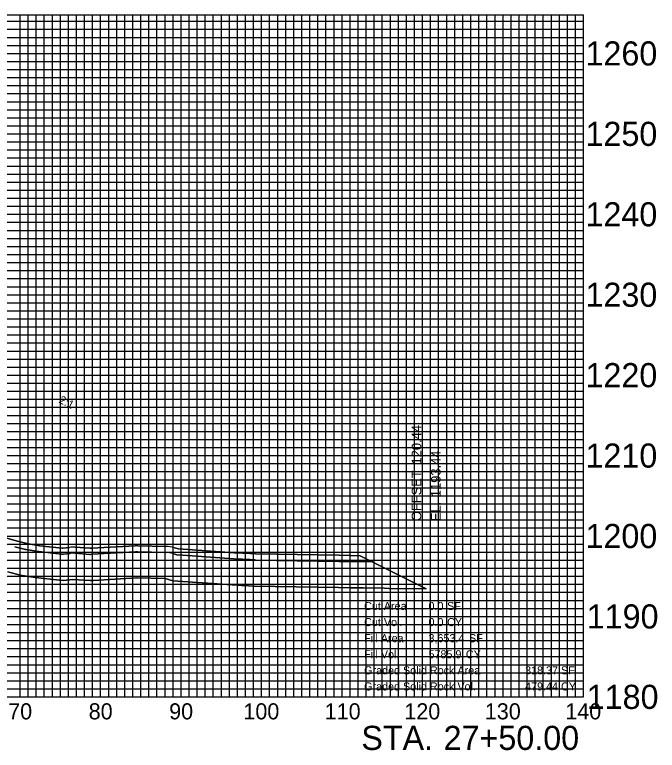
# Model space of a CAD drawing. Extents: x -109 to 149, y 1173 to 1269.
# Drawn here: x 69.3 to 149.2, y 1173.4 to 1264.8 of the extents above; entities that cross this region are included whole.
import ezdxf

# ---------------------------------------------------------------- set-up
doc = ezdxf.new("R2010")
doc.units = 0
for name, color, linetype in [('DES - SHEET - Light Grid', 7, 'Continuous'), ('DES - SHEET - Linework', 7, 'Continuous'), ('DES - TRAN - Proposed Layout Patterning', 7, 'Continuous'), ('DES - XS - Proposed - Finished Grade Slopes Text', 7, 'Continuous'), ('DES - XS - Proposed - Text', 7, 'Continuous')]:
    doc.layers.add(name, color=color, linetype=linetype)

msp = doc.modelspace()

# ---------------------------------------------------------------- linework, layer by layer
at = {"layer": 'DES - SHEET - Light Grid'}
for p, q in [((-100, 1264), (140, 1264)), ((71, 1180), (71, 1264.814)), ((72, 1180), (72, 1264.814)), ((73, 1180), (73, 1264.814)), ((74, 1180), (74, 1264.814)), ((75, 1180), (75, 1264.814)), ((76, 1180), (76, 1264.814)), ((77, 1180), (77, 1264.814)), ((78, 1180), (78, 1264.814)), ((79, 1180), (79, 1264.814)), ((81, 1180), (81, 1264.814)), ((82, 1180), (82, 1264.814)), ((83, 1180), (83, 1264.814)), ((84, 1180), (84, 1264.814)), ((85, 1180), (85, 1264.814)), ((86, 1180), (86, 1264.814)), ((87, 1180), (87, 1264.814)), ((88, 1180), (88, 1264.814)), ((89, 1180), (89, 1264.814)), ((91, 1180), (91, 1264.814)), ((92, 1180), (92, 1264.814)), ((93, 1180), (93, 1264.814)), ((94, 1180), (94, 1264.814)), ((95, 1180), (95, 1264.814)), ((96, 1180), (96, 1264.814)), ((97, 1180), (97, 1264.814)), ((98, 1180), (98, 1264.814)), ((99, 1180), (99, 1264.814)), ((101, 1180), (101, 1264.814)), ((102, 1180), (102, 1264.814)), ((103, 1180), (103, 1264.814)), ((104, 1180), (104, 1264.814)), ((105, 1180), (105, 1264.814)), ((106, 1180), (106, 1264.814)), ((107, 1180), (107, 1264.814)), ((108, 1180), (108, 1264.814)), ((109, 1180), (109, 1264.814)), ((111, 1180), (111, 1264.814)), ((112, 1180), (112, 1264.814)), ((113, 1180), (113, 1264.814)), ((114, 1180), (114, 1264.814)), ((115, 1180), (115, 1264.814)), ((116, 1180), (116, 1264.814)), ((117, 1180), (117, 1264.814)), ((118, 1180), (118, 1264.814)), ((119, 1180), (119, 1264.814)), ((121, 1180), (121, 1264.814)), ((122, 1180), (122, 1264.814)), ((123, 1180), (123, 1264.814)), ((124, 1180), (124, 1264.814)), ((125, 1180), (125, 1264.814)), ((126, 1180), (126, 1264.814)), ((127, 1180), (127, 1264.814)), ((128, 1180), (128, 1264.814)), ((129, 1180), (129, 1264.814)), ((131, 1180), (131, 1264.814)), ((132, 1180), (132, 1264.814)), ((133, 1180), (133, 1264.814)), ((134, 1180), (134, 1264.814)), ((135, 1180), (135, 1264.814)), ((136, 1180), (136, 1264.814)), ((137, 1180), (137, 1264.814)), ((138, 1180), (138, 1264.814)), ((139, 1180), (139, 1264.814)), ((-100, 1263), (140, 1263)), ((-100, 1262), (140, 1262)), ((-100, 1261), (140, 1261)), ((-100, 1259), (140, 1259)), ((-100, 1258), (140, 1258)), ((-100, 1257), (140, 1257)), ((-100, 1256), (140, 1256)), ((-100, 1255), (140, 1255)), ((-100, 1254), (140, 1254)), ((-100, 1253), (140, 1253)), ((-100, 1252), (140, 1252)), ((-100, 1251), (140, 1251)), ((-100, 1249), (140, 1249)), ((-100, 1248), (140, 1248)), ((-100, 1247), (140, 1247)), ((-100, 1246), (140, 1246)), ((-100, 1245), (140, 1245)), ((-100, 1244), (140, 1244)), ((-100, 1243), (140, 1243)), ((-100, 1242), (140, 1242)), ((-100, 1241), (140, 1241)), ((-100, 1239), (140, 1239)), ((-100, 1238), (140, 1238)), ((-100, 1237), (140, 1237)), ((-100, 1236), (140, 1236)), ((-100, 1235), (140, 1235)), ((-100, 1234), (140, 1234)), ((-100, 1233), (140, 1233)), ((-100, 1232), (140, 1232)), ((-100, 1231), (140, 1231)), ((-100, 1229), (140, 1229)), ((-100, 1228), (140, 1228)), ((-100, 1227), (140, 1227)), ((-100, 1226), (140, 1226)), ((-100, 1225), (140, 1225)), ((-100, 1224), (140, 1224)), ((-100, 1223), (140, 1223)), ((-100, 1222), (140, 1222)), ((-100, 1221), (140, 1221)), ((-100, 1219), (140, 1219)), ((-100, 1218), (140, 1218)), ((-100, 1217), (140, 1217)), ((-100, 1216), (140, 1216)), ((-100, 1215), (140, 1215)), ((-100, 1214), (140, 1214)), ((-100, 1213), (140, 1213)), ((-100, 1212), (140, 1212)), ((-100, 1211), (140, 1211)), ((-100, 1209), (140, 1209)), ((-100, 1208), (140, 1208)), ((-100, 1207), (140, 1207)), ((-100, 1206), (140, 1206)), ((-100, 1205), (140, 1205)), ((-100, 1204), (140, 1204)), ((-100, 1203), (140, 1203)), ((-100, 1202), (140, 1202)), ((-100, 1201), (140, 1201)), ((-100, 1199), (140, 1199)), ((-100, 1198), (140, 1198)), ((-100, 1197), (140, 1197)), ((-100, 1196), (140, 1196)), ((-100, 1195), (140, 1195)), ((-100, 1194), (140, 1194)), ((-100, 1193), (140, 1193)), ((-100, 1192), (140, 1192)), ((-100, 1191), (140, 1191)), ((-100, 1189), (140, 1189)), ((-100, 1188), (140, 1188)), ((-100, 1187), (140, 1187)), ((-100, 1186), (140, 1186)), ((-100, 1185), (140, 1185)), ((-100, 1184), (140, 1184)), ((-100, 1183), (140, 1183)), ((-100, 1182), (140, 1182)), ((-100, 1181), (140, 1181))]:
    msp.add_line(p, q, dxfattribs=at)
at = {"layer": 'DES - SHEET - Linework'}
for p, q in [((-100, 1264.814), (140, 1264.814)), ((70, 1180), (70, 1264.814)), ((80, 1180), (80, 1264.814)), ((90, 1180), (90, 1264.814)), ((100, 1180), (100, 1264.814)), ((110, 1180), (110, 1264.814)), ((120, 1180), (120, 1264.814)), ((130, 1180), (130, 1264.814)), ((140, 1180), (140, 1264.814)), ((-100, 1260), (140, 1260)), ((-100, 1250), (140, 1250)), ((-100, 1240), (140, 1240)), ((-100, 1230), (140, 1230)), ((-100, 1220), (140, 1220)), ((-100, 1210), (140, 1210)), ((-100, 1200), (140, 1200)), ((-100, 1190), (140, 1190)), ((-100, 1180), (140, 1180))]:
    msp.add_line(p, q, dxfattribs=at)
at = {"layer": 'DES - TRAN - Proposed Layout Patterning'}
for p, q in [((70.653, 1198.333), (69.322, 1198.673)), ((69.322, 1198.673), (70.653, 1198.333)), ((69.322, 1198.673), (70.653, 1198.333)), ((70.653, 1198.333), (69.322, 1198.673)), ((70.653, 1198.333), (69.322, 1198.673)), ((72.294, 1198.058), (70.716, 1198.32)), ((70.716, 1198.32), (72.294, 1198.058)), ((70.716, 1198.32), (72.294, 1198.058)), ((72.294, 1198.058), (70.716, 1198.32)), ((72.294, 1198.058), (70.716, 1198.32)), ((84.277, 1198.79), (78.876, 1198.482)), ((78.876, 1198.482), (84.277, 1198.79)), ((78.876, 1198.482), (84.277, 1198.79)), ((78.876, 1198.482), (84.277, 1198.79)), ((88.136, 1198.705), (84.608, 1198.796)), ((84.608, 1198.796), (88.136, 1198.705)), ((84.608, 1198.796), (88.136, 1198.705)), ((84.608, 1198.796), (88.136, 1198.705)), ((75.117, 1197.751), (72.336, 1198.053)), ((72.336, 1198.053), (75.117, 1197.751)), ((72.336, 1198.053), (75.117, 1197.751)), ((75.117, 1197.751), (72.336, 1198.053)), ((75.117, 1197.751), (72.336, 1198.053)), ((75.251, 1197.743), (75.16, 1197.748)), ((75.16, 1197.748), (75.251, 1197.743)), ((75.16, 1197.748), (75.251, 1197.743)), ((75.251, 1197.743), (75.16, 1197.748)), ((75.251, 1197.743), (75.16, 1197.748)), ((76.213, 1197.836), (75.368, 1197.746)), ((75.368, 1197.746), (76.213, 1197.836)), ((75.368, 1197.746), (76.213, 1197.836)), ((76.213, 1197.836), (75.368, 1197.746)), ((76.213, 1197.836), (75.368, 1197.746)), ((78.641, 1197.721), (76.775, 1197.847)), ((76.775, 1197.847), (78.641, 1197.721)), ((76.775, 1197.847), (78.641, 1197.721)), ((78.641, 1197.721), (76.775, 1197.847)), ((78.641, 1197.721), (76.775, 1197.847)), ((78.881, 1197.731), (78.743, 1197.721)), ((78.743, 1197.721), (78.881, 1197.731)), ((78.743, 1197.721), (78.881, 1197.731)), ((78.881, 1197.731), (78.743, 1197.721)), ((78.881, 1197.731), (78.743, 1197.721)), ((84.319, 1198.042), (78.918, 1197.733)), ((78.918, 1197.733), (84.319, 1198.042)), ((78.918, 1197.733), (84.319, 1198.042)), ((84.319, 1198.042), (78.918, 1197.733)), ((84.319, 1198.042), (78.918, 1197.733)), ((88.117, 1197.955), (84.589, 1198.046)), ((84.589, 1198.046), (88.117, 1197.955)), ((84.589, 1198.046), (88.117, 1197.955)), ((88.117, 1197.955), (84.589, 1198.046)), ((88.117, 1197.955), (84.589, 1198.046)), ((89.477, 1197.669), (88.951, 1197.824)), ((88.951, 1197.824), (89.477, 1197.669)), ((88.951, 1197.824), (89.477, 1197.669)), ((89.477, 1197.669), (88.951, 1197.824)), ((89.477, 1197.669), (88.951, 1197.824)), ((96.56, 1197.173), (89.638, 1197.64)), ((89.638, 1197.64), (96.56, 1197.173)), ((89.638, 1197.64), (96.56, 1197.173)), ((96.56, 1197.173), (89.638, 1197.64)), ((96.56, 1197.173), (89.638, 1197.64)), ((97.615, 1197.101), (96.565, 1197.173)), ((96.565, 1197.173), (97.615, 1197.101)), ((96.565, 1197.173), (97.615, 1197.101)), ((97.615, 1197.101), (96.565, 1197.173)), ((97.615, 1197.101), (96.565, 1197.173)), ((111.087, 1197.572), (109.631, 1197.599)), ((109.631, 1197.599), (111.087, 1197.572)), ((109.631, 1197.599), (111.087, 1197.572)), ((109.631, 1197.599), (111.087, 1197.572)), ((112.228, 1197.55), (111.089, 1197.572)), ((120.445, 1193.442), (112.228, 1197.55)), ((98.505, 1197.064), (97.635, 1197.1)), ((97.635, 1197.1), (98.505, 1197.064)), ((97.635, 1197.1), (98.505, 1197.064)), ((98.505, 1197.064), (97.635, 1197.1)), ((98.505, 1197.064), (97.635, 1197.1)), ((99.201, 1197.018), (98.587, 1197.059)), ((98.587, 1197.059), (99.201, 1197.018)), ((98.587, 1197.059), (99.201, 1197.018)), ((99.201, 1197.018), (98.587, 1197.059)), ((99.201, 1197.018), (98.587, 1197.059)), ((109.609, 1196.85), (99.239, 1197.016)), ((99.239, 1197.016), (109.609, 1196.85)), ((99.239, 1197.016), (109.609, 1196.85)), ((109.609, 1196.85), (99.239, 1197.016)), ((109.609, 1196.85), (99.239, 1197.016)), ((111.073, 1196.822), (109.617, 1196.849)), ((109.617, 1196.849), (111.073, 1196.822)), ((109.617, 1196.849), (111.073, 1196.822)), ((111.073, 1196.822), (109.617, 1196.849)), ((111.073, 1196.822), (109.617, 1196.849)), ((113.788, 1196.77), (111.075, 1196.822))]:
    msp.add_line(p, q, dxfattribs=at)
for points in [[(76.133, 1198.582), (75.289, 1198.492), (75.198, 1198.497), (72.417, 1198.798), (70.839, 1199.059), (69.508, 1199.4), (67.176, 1200.078)], [(67.176, 1200.078), (69.508, 1199.4), (70.839, 1199.059), (72.417, 1198.798), (75.198, 1198.497), (75.289, 1198.492), (76.133, 1198.582)], [(67.176, 1200.078), (69.508, 1199.4), (70.839, 1199.059), (72.417, 1198.798), (75.198, 1198.497), (75.289, 1198.492), (76.133, 1198.582)], [(67.176, 1200.078), (69.508, 1199.4), (70.839, 1199.059), (72.417, 1198.798), (75.198, 1198.497), (75.289, 1198.492), (76.133, 1198.582)], [(78.83, 1198.479), (78.691, 1198.469), (76.825, 1198.595)], [(76.825, 1198.595), (78.691, 1198.469), (78.83, 1198.479)], [(76.825, 1198.595), (78.691, 1198.469), (78.83, 1198.479)], [(76.825, 1198.595), (78.691, 1198.469), (78.83, 1198.479)], [(96.61, 1197.922), (89.689, 1198.388), (89.163, 1198.543)], [(89.163, 1198.543), (89.689, 1198.388), (96.61, 1197.922)], [(89.163, 1198.543), (89.689, 1198.388), (96.61, 1197.922)], [(89.163, 1198.543), (89.689, 1198.388), (96.61, 1197.922)], [(111.089, 1197.572), (112.228, 1197.55), (120.445, 1193.442), (120.445, 1193.442), (115.813, 1193.464), (115.284, 1193.5), (112.623, 1193.542), (111.013, 1193.573), (109.556, 1193.6), (99.086, 1193.768), (98.369, 1193.816), (97.446, 1193.855), (96.342, 1193.931), (88.981, 1194.427), (88.033, 1194.706), (84.505, 1194.797), (79.104, 1194.488), (78.694, 1194.46), (76.556, 1194.604), (75.401, 1194.481), (74.882, 1194.508), (71.874, 1194.834), (70.015, 1195.141), (68.454, 1195.541)], [(98.536, 1197.813), (97.667, 1197.849), (96.616, 1197.921)], [(96.616, 1197.921), (97.667, 1197.849), (98.536, 1197.813)], [(96.616, 1197.921), (97.667, 1197.849), (98.536, 1197.813)], [(96.616, 1197.921), (97.667, 1197.849), (98.536, 1197.813)], [(109.621, 1197.599), (99.252, 1197.766), (98.637, 1197.807)], [(98.637, 1197.807), (99.252, 1197.766), (109.621, 1197.599)], [(98.637, 1197.807), (99.252, 1197.766), (109.621, 1197.599)], [(98.637, 1197.807), (99.252, 1197.766), (109.621, 1197.599)], [(111.089, 1197.572), (112.228, 1197.55), (113.788, 1196.77), (111.075, 1196.822)], [(111.089, 1197.572), (112.228, 1197.55), (113.788, 1196.77), (111.075, 1196.822)], [(111.075, 1196.822), (113.788, 1196.77), (120.445, 1193.442), (120.445, 1193.442), (115.813, 1193.464), (115.284, 1193.5), (112.623, 1193.542), (111.013, 1193.573), (109.556, 1193.6), (99.086, 1193.768), (98.369, 1193.816), (97.446, 1193.855), (96.342, 1193.931), (88.981, 1194.427), (88.033, 1194.706), (84.505, 1194.797), (79.104, 1194.488), (78.694, 1194.46), (76.556, 1194.604), (75.401, 1194.481), (74.882, 1194.508), (71.874, 1194.834), (70.015, 1195.141), (68.454, 1195.541)], [(111.075, 1196.822), (113.788, 1196.77), (120.445, 1193.442), (120.445, 1193.442), (115.813, 1193.464), (115.284, 1193.5), (112.623, 1193.542), (111.013, 1193.573), (109.556, 1193.6), (99.086, 1193.768), (98.369, 1193.816), (97.446, 1193.855), (96.342, 1193.931), (88.981, 1194.427), (88.033, 1194.706), (84.505, 1194.797), (79.104, 1194.488), (78.694, 1194.46), (76.556, 1194.604), (75.401, 1194.481), (74.882, 1194.508), (71.874, 1194.834), (70.015, 1195.141), (68.454, 1195.541)], [(68.454, 1195.541), (70.015, 1195.141), (71.874, 1194.834), (74.882, 1194.508), (75.401, 1194.481), (76.556, 1194.604), (78.694, 1194.46), (79.104, 1194.488), (84.505, 1194.797), (88.033, 1194.706), (88.981, 1194.427), (96.342, 1193.931), (97.446, 1193.855), (98.369, 1193.816), (99.086, 1193.768), (109.556, 1193.6), (111.013, 1193.573), (112.623, 1193.542), (115.284, 1193.5), (115.813, 1193.464), (120.445, 1193.442)]]:
    msp.add_lwpolyline(points, dxfattribs=at)
for centre, radius, start, end in [((70.839, 1199.059), 0.75, 255.64195, 260.59904), ((70.839, 1199.059), 0.75, 255.64195, 260.59904), ((70.839, 1199.059), 0.75, 255.64195, 260.59904), ((70.839, 1199.059), 0.75, 255.64195, 260.59904), ((70.839, 1199.059), 0.75, 255.64195, 260.59904), ((76.556, 1194.604), 4, 86.14163, 96.06419), ((76.556, 1194.604), 4, 86.14163, 96.06419), ((76.556, 1194.604), 4, 86.14163, 96.06419), ((76.556, 1194.604), 4, 86.14163, 96.06419), ((79.104, 1194.488), 4, 93.27244, 93.92782), ((79.104, 1194.488), 4, 93.27244, 93.92782), ((79.104, 1194.488), 4, 93.27244, 93.92782), ((79.104, 1194.488), 4, 93.27244, 93.92782), ((84.505, 1194.797), 4, 88.52132, 93.27244), ((84.505, 1194.797), 4, 88.52132, 93.27244), ((84.505, 1194.797), 4, 88.52132, 93.27244), ((84.505, 1194.797), 4, 88.52132, 93.27244), ((88.033, 1194.706), 4, 73.59406, 88.52132), ((88.033, 1194.706), 4, 73.59406, 88.52132), ((88.033, 1194.706), 4, 73.59406, 88.52132), ((88.033, 1194.706), 4, 73.59406, 88.52132), ((72.417, 1198.798), 0.75, 260.59904, 263.81215), ((72.417, 1198.798), 0.75, 260.59904, 263.81215), ((72.417, 1198.798), 0.75, 260.59904, 263.81215), ((72.417, 1198.798), 0.75, 260.59904, 263.81215), ((72.417, 1198.798), 0.75, 260.59904, 263.81215), ((75.198, 1198.497), 0.75, 263.81215, 267.12595), ((75.198, 1198.497), 0.75, 263.81215, 267.12595), ((75.198, 1198.497), 0.75, 263.81215, 267.12595), ((75.198, 1198.497), 0.75, 263.81215, 267.12595), ((75.198, 1198.497), 0.75, 263.81215, 267.12595), ((75.289, 1198.492), 0.75, 267.12595, 276.06419), ((75.289, 1198.492), 0.75, 267.12595, 276.06419), ((75.289, 1198.492), 0.75, 267.12595, 276.06419), ((75.289, 1198.492), 0.75, 267.12595, 276.06419), ((75.289, 1198.492), 0.75, 267.12595, 276.06419), ((76.556, 1194.604), 3.25, 86.14163, 96.06419), ((76.556, 1194.604), 3.25, 86.14163, 96.06419), ((76.556, 1194.604), 3.25, 86.14163, 96.06419), ((76.556, 1194.604), 3.25, 86.14163, 96.06419), ((76.556, 1194.604), 3.25, 86.14163, 96.06419), ((78.691, 1198.469), 0.75, 266.14163, 273.92782), ((78.691, 1198.469), 0.75, 266.14163, 273.92782), ((78.691, 1198.469), 0.75, 266.14163, 273.92782), ((78.691, 1198.469), 0.75, 266.14163, 273.92782), ((78.691, 1198.469), 0.75, 266.14163, 273.92782), ((79.104, 1194.488), 3.25, 93.27244, 93.92782), ((79.104, 1194.488), 3.25, 93.27244, 93.92782), ((79.104, 1194.488), 3.25, 93.27244, 93.92782), ((79.104, 1194.488), 3.25, 93.27244, 93.92782), ((79.104, 1194.488), 3.25, 93.27244, 93.92782), ((84.505, 1194.797), 3.25, 88.52132, 93.27244), ((84.505, 1194.797), 3.25, 88.52132, 93.27244), ((84.505, 1194.797), 3.25, 88.52132, 93.27244), ((84.505, 1194.797), 3.25, 88.52132, 93.27244), ((84.505, 1194.797), 3.25, 88.52132, 93.27244), ((88.033, 1194.706), 3.25, 73.59406, 88.52132), ((88.033, 1194.706), 3.25, 73.59406, 88.52132), ((88.033, 1194.706), 3.25, 73.59406, 88.52132), ((88.033, 1194.706), 3.25, 73.59406, 88.52132), ((88.033, 1194.706), 3.25, 73.59406, 88.52132), ((89.689, 1198.388), 0.75, 253.59406, 266.14464), ((89.689, 1198.388), 0.75, 253.59406, 266.14464), ((89.689, 1198.388), 0.75, 253.59406, 266.14464), ((89.689, 1198.388), 0.75, 253.59406, 266.14464), ((89.689, 1198.388), 0.75, 253.59406, 266.14464), ((96.342, 1193.931), 3.25, 86.06546, 86.14464), ((96.342, 1193.931), 3.25, 86.06546, 86.14464), ((96.342, 1193.931), 3.25, 86.06546, 86.14464), ((96.342, 1193.931), 3.25, 86.06546, 86.14464), ((96.342, 1193.931), 3.25, 86.06546, 86.14464), ((96.342, 1193.931), 4, 86.06546, 86.14464), ((96.342, 1193.931), 4, 86.06546, 86.14464), ((96.342, 1193.931), 4, 86.06546, 86.14464), ((96.342, 1193.931), 4, 86.06546, 86.14464), ((98.369, 1193.816), 4, 86.17098, 87.61441), ((98.369, 1193.816), 4, 86.17098, 87.61441), ((98.369, 1193.816), 4, 86.17098, 87.61441), ((98.369, 1193.816), 4, 86.17098, 87.61441), ((109.556, 1193.6), 4, 88.92715, 89.07805), ((109.556, 1193.6), 4, 88.92715, 89.07805), ((109.556, 1193.6), 4, 88.92715, 89.07805), ((109.556, 1193.6), 4, 88.92715, 89.07805), ((111.013, 1193.573), 4, 88.89886, 88.92715), ((111.013, 1193.573), 4, 88.89886, 88.92715), ((111.013, 1193.573), 4, 88.89886, 88.92715), ((111.013, 1193.573), 4, 88.89886, 88.92715), ((97.667, 1197.849), 0.75, 266.06546, 267.61441), ((97.667, 1197.849), 0.75, 266.06546, 267.61441), ((97.667, 1197.849), 0.75, 266.06546, 267.61441), ((97.667, 1197.849), 0.75, 266.06546, 267.61441), ((97.667, 1197.849), 0.75, 266.06546, 267.61441), ((98.369, 1193.816), 3.25, 86.17098, 87.61441), ((98.369, 1193.816), 3.25, 86.17098, 87.61441), ((98.369, 1193.816), 3.25, 86.17098, 87.61441), ((98.369, 1193.816), 3.25, 86.17098, 87.61441), ((98.369, 1193.816), 3.25, 86.17098, 87.61441), ((99.252, 1197.766), 0.75, 266.17098, 269.07805), ((99.252, 1197.766), 0.75, 266.17098, 269.07805), ((99.252, 1197.766), 0.75, 266.17098, 269.07805), ((99.252, 1197.766), 0.75, 266.17098, 269.07805), ((99.252, 1197.766), 0.75, 266.17098, 269.07805), ((109.556, 1193.6), 3.25, 88.92715, 89.07805), ((109.556, 1193.6), 3.25, 88.92715, 89.07805), ((109.556, 1193.6), 3.25, 88.92715, 89.07805), ((109.556, 1193.6), 3.25, 88.92715, 89.07805), ((109.556, 1193.6), 3.25, 88.92715, 89.07805), ((111.013, 1193.573), 3.25, 88.89886, 88.92715), ((111.013, 1193.573), 3.25, 88.89886, 88.92715), ((111.013, 1193.573), 3.25, 88.89886, 88.92715), ((111.013, 1193.573), 3.25, 88.89886, 88.92715), ((111.013, 1193.573), 3.25, 88.89886, 88.92715)]:
    msp.add_arc(centre, radius, start, end, dxfattribs=at)

# ---------------------------------------------------------------- texts
at = {"layer": 'DES - XS - Proposed - Finished Grade Slopes Text'}
for s, height, rotation, p in [('2:1', 1, 333.43495, (74.719, 1216.605)), ("120.44'", 1.2, 90, (119.845, 1208.892)), ('1193.44', 1.2, 90, (122.245, 1204.824)), ('OFFSET ', 1.2, 90, (119.845, 1201.842)), ('EL. ', 1.2, 90, (122.245, 1201.842))]:
    msp.add_text(s, height=height, rotation=rotation, dxfattribs=at).set_placement(p)
at = {"layer": 'DES - XS - Proposed - Text'}
for s, height, p in [('1260', 3, (140.241, 1258.5)), ('1250', 3, (140.241, 1248.5)), ('1240', 3, (140.241, 1238.5)), ('1230', 3, (140.241, 1228.5)), ('1220', 3, (140.241, 1218.5)), ('1210', 3, (140.241, 1208.5)), ('1200', 3, (140.241, 1198.5)), ('Cut Area', 1, (112.737, 1190.796)), ('0.0', 1, (120.737, 1190.796)), (' SF', 1, (122.678, 1190.796)), ('1190', 3, (140.396, 1188.5)), ('Cut Vol.', 1, (112.737, 1188.796)), ('0.0', 1, (120.737, 1188.796)), (' CY', 1, (122.678, 1188.796)), ('Fill Area', 1, (112.737, 1186.796)), ('3,653.4', 1, (120.737, 1186.796)), (' SF', 1, (125.396, 1186.796)), ('Fill Vol.', 1, (112.737, 1184.796)), ('5785.9', 1, (120.737, 1184.796)), (' CY', 1, (125.008, 1184.796)), ('Graded Solid Rock Area', 1, (112.737, 1182.796)), ('318.37 SF', 1, (132.737, 1182.796)), ('Graded Solid Rock Vol.', 1, (112.737, 1180.796)), ('479.44 CY', 1, (132.737, 1180.796)), ('1180', 3, (140.396, 1178.5)), ('70', 2, (68.514, 1177.2)), ('80', 2, (78.514, 1177.2)), ('90', 2, (88.514, 1177.2)), ('100', 2, (97.737, 1177.2)), ('110', 2, (107.841, 1177.2)), ('120', 2, (117.737, 1177.2)), ('130', 2, (127.737, 1177.2)), ('140', 2, (137.737, 1177.2)), (' STA. ', 3, (111.276, 1173.4)), ('27+50.00', 3, (122.611, 1173.4))]:
    msp.add_text(s, height=height, dxfattribs=at).set_placement(p)

doc.saveas('drawing.dxf')
